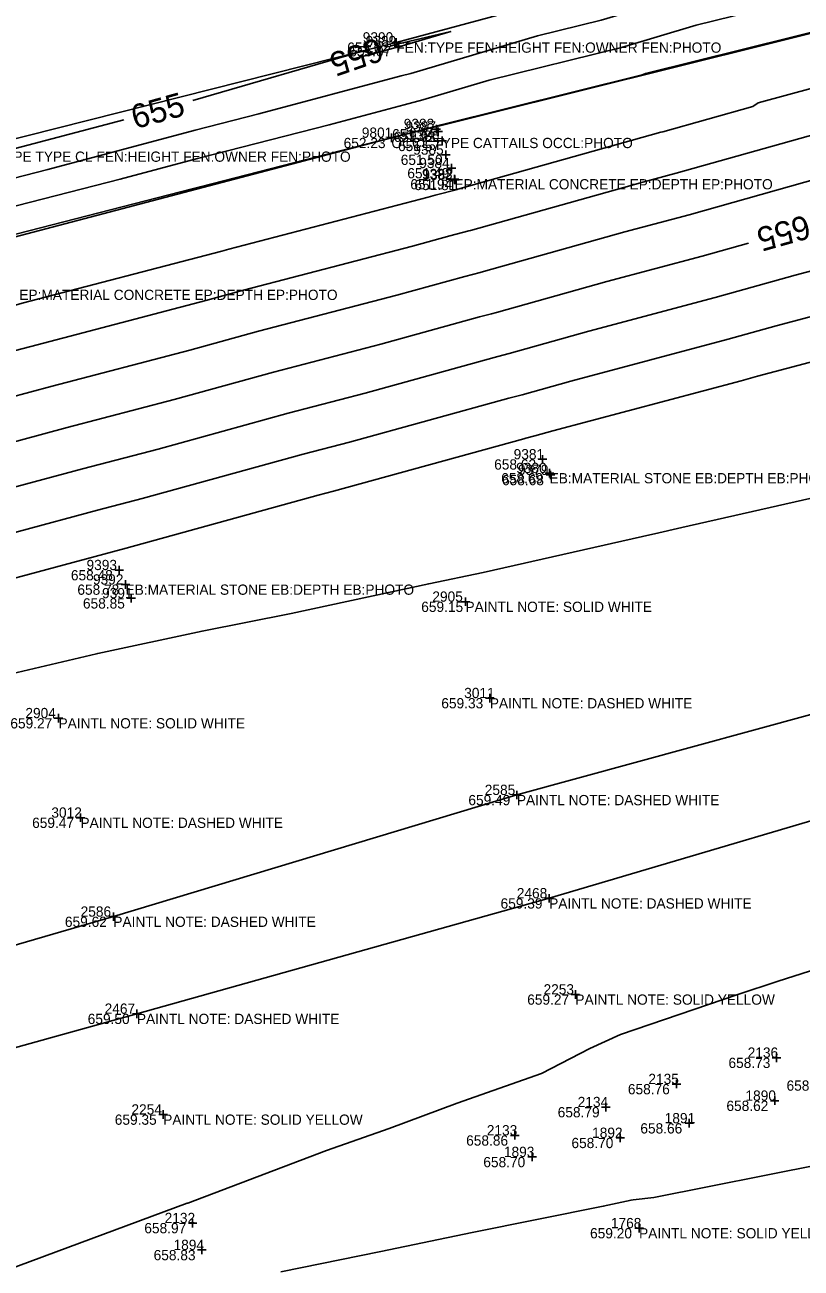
# Model space of a CAD drawing. Extents: x 2129350 to 2137777, y 657588 to 659885.
# Drawn here: x 2134795.8 to 2134886.7, y 659166.7 to 659312.2 of the extents above; entities that cross this region are included whole.
import ezdxf

# ---------------------------------------------------------------- set-up
doc = ezdxf.new("R2010")
doc.units = 0
for name, color, linetype in [('DT_X_Contour_Major', 7, 'Continuous'), ('DT_X_Contour_Minor', 7, 'Continuous'), ('DT_X_TIN_Hull', 7, 'Continuous'), ('PV_X_COP', 7, 'Continuous'), ('SV_X_Occupation_Line', 7, 'Continuous'), ('SV_X_Shot_Marker', 7, 'Continuous'), ('SV_X_Text_Comment', 7, 'Continuous'), ('SV_X_Text_Elevation', 7, 'Continuous'), ('SV_X_Text_Name', 7, 'Continuous')]:
    doc.layers.add(name, color=color, linetype=linetype)

msp = doc.modelspace()

# ---------------------------------------------------------------- linework, layer by layer
at = {"layer": 'DT_X_Contour_Major'}
for points in [[(2134839.53, 659309.65), (2134839.56, 659309.66), (2134845.65, 659311.45), (2134839.38, 659309.98), (2134838.56, 659309.72)], [(2134815.45, 659303.39), (2134835.85, 659309.3)], [(2134834.42, 659308.29), (2134839.53, 659309.65)], [(2134710.82, 659275.11), (2134722.14, 659278.72), (2134730.19, 659280.83), (2134741.44, 659283.77), (2134755.5, 659287.45), (2134775.47, 659292.74), (2134788.82, 659296.22), (2134790.45, 659296.66), (2134807.36, 659301.13)], [(2134784.02, 659260.55), (2134789.32, 659262.01), (2134800.75, 659265.09), (2134813.25, 659268.35), (2134824.88, 659271.56), (2134837.48, 659274.85), (2134849.02, 659278.03), (2134850.43, 659278.4), (2134851, 659278.55), (2134863.93, 659282.18), (2134875.1, 659285.15), (2134880.54, 659286.68)]]:
    msp.add_lwpolyline(points, dxfattribs=at)
at = {"layer": 'DT_X_Contour_Minor'}
for points in [[(2134699.42, 659268.63), (2134712.76, 659272.09), (2134713.84, 659272.45), (2134717.95, 659274.17), (2134736.51, 659279.04), (2134742.02, 659280.41), (2134759.71, 659285.04), (2134766.23, 659286.82), (2134783.58, 659291.38), (2134789.78, 659293.07), (2134791.58, 659293.55), (2134798.46, 659295.31), (2134815.72, 659299.91), (2134823.16, 659301.82), (2134839.85, 659306.26), (2134840.98, 659306.55), (2134855.81, 659310.93), (2134863.28, 659312.79), (2134880.29, 659317.84), (2134887.25, 659319.57)], [(2134889.82, 659316.01), (2134874.38, 659312.18), (2134865.67, 659309.6), (2134850.17, 659305.74), (2134842.4, 659303.44), (2134840.18, 659302.87), (2134831.43, 659300.54), (2134816.01, 659296.59), (2134806.93, 659294.17), (2134791.84, 659290.31), (2134790.89, 659290.05), (2134777.18, 659286.32), (2134768.19, 659283.96), (2134753, 659279.82), (2134744.06, 659277.47), (2134730.43, 659274.1), (2134720.3, 659271.44), (2134709.4, 659266.88)], [(2134891.42, 659312.22), (2134868.47, 659306.52), (2134868.06, 659306.4), (2134844.53, 659300.54), (2134843.83, 659300.34), (2134840.5, 659299.49), (2134839.71, 659299.27), (2134816.3, 659293.28), (2134815.39, 659293.03), (2134792.09, 659287.06), (2134791.99, 659287.04), (2134770.78, 659281.26), (2134770.15, 659281.1), (2134746.3, 659274.59), (2134746.09, 659274.54), (2134724.35, 659269.15), (2134722.66, 659268.7), (2134720.39, 659267.75), (2134709.21, 659264.82)], [(2134702.5, 659254.36), (2134725.66, 659260.59), (2134726.7, 659260.87), (2134748.27, 659266.68), (2134748.42, 659266.72), (2134771.59, 659273.08), (2134772.52, 659273.33), (2134794.7, 659279.43), (2134795.46, 659279.63), (2134818.85, 659285.74), (2134819.65, 659285.96), (2134843.02, 659292.06), (2134843.84, 659292.29), (2134846.43, 659292.97), (2134846.48, 659292.98), (2134870.25, 659299.65), (2134870.51, 659299.72), (2134881.04, 659302.68), (2134881.64, 659303.12), (2134895.16, 659306.79)], [(2134706.8, 659250.25), (2134726.55, 659255.56), (2134731.06, 659256.76), (2134749.39, 659261.7), (2134750.02, 659261.86), (2134769.68, 659267.27), (2134774.12, 659268.46), (2134792.9, 659273.62), (2134797.22, 659274.78), (2134816.98, 659279.94), (2134821.39, 659281.16), (2134841.17, 659286.32), (2134845.56, 659287.53), (2134847.77, 659288.11), (2134847.98, 659288.17), (2134868.14, 659293.83), (2134872.04, 659294.86), (2134892.65, 659300.66)], [(2134703.32, 659244.07), (2134711.11, 659246.14), (2134727.44, 659250.53), (2134735.43, 659252.66), (2134750.5, 659256.72), (2134751.61, 659257.01), (2134767.78, 659261.45), (2134775.72, 659263.59), (2134791.11, 659267.82), (2134798.99, 659269.93), (2134815.11, 659274.15), (2134823.14, 659276.36), (2134839.33, 659280.58), (2134847.29, 659282.78), (2134849.1, 659283.25), (2134849.49, 659283.36), (2134866.04, 659288.01), (2134873.57, 659290), (2134890.43, 659294.75)], [(2134705.11, 659234.04), (2134719.72, 659237.92), (2134729.22, 659240.48), (2134744.15, 659244.44), (2134752.73, 659246.75), (2134754.79, 659247.3), (2134763.96, 659249.82), (2134778.93, 659253.84), (2134787.52, 659256.21), (2134802.51, 659260.24), (2134811.38, 659262.55), (2134826.63, 659266.76), (2134835.64, 659269.11), (2134850.75, 659273.27), (2134851.76, 659273.54), (2134852.51, 659273.74), (2134861.82, 659276.36), (2134876.63, 659280.29), (2134886, 659282.92), (2134900.74, 659286.83)], [(2134706.01, 659229.02), (2134724.03, 659233.81), (2134730.11, 659235.45), (2134748.51, 659240.34), (2134753.84, 659241.77), (2134756.38, 659242.44), (2134762.06, 659244), (2134780.53, 659248.97), (2134785.73, 659250.4), (2134804.28, 659255.39), (2134809.52, 659256.76), (2134828.38, 659261.96), (2134833.79, 659263.37), (2134852.47, 659268.52), (2134853.1, 659268.68), (2134854.01, 659268.93), (2134859.71, 659270.53), (2134878.15, 659275.43), (2134883.78, 659277.01), (2134902.3, 659281.92)], [(2134706.91, 659224.01), (2134728.34, 659229.7), (2134731.01, 659230.42), (2134752.87, 659236.23), (2134754.96, 659236.79), (2134757.97, 659237.59), (2134760.15, 659238.19), (2134782.13, 659244.1), (2134783.94, 659244.6), (2134806.04, 659250.54), (2134807.65, 659250.96), (2134830.12, 659257.16), (2134831.94, 659257.63), (2134854.2, 659263.77), (2134854.43, 659263.83), (2134855.52, 659264.13), (2134857.6, 659264.71), (2134879.68, 659270.57), (2134881.56, 659271.1), (2134903.85, 659277.01)], [(2134708.88, 659216.82), (2134732.14, 659222.06), (2134735.18, 659222.69), (2134755.58, 659227.24), (2134755.62, 659227.25), (2134758.2, 659227.83), (2134764.28, 659229.25), (2134781.18, 659233.22), (2134790.18, 659235.32), (2134804.17, 659238.6), (2134804.31, 659238.64), (2134816.54, 659241.25), (2134826.95, 659243.32), (2134843.07, 659246.8), (2134849.45, 659248.09), (2134869.33, 659252.61), (2134869.5, 659252.64), (2134872.7, 659253.37), (2134895.12, 659258.47)], [(2134892.21, 659202.86), (2134883.98, 659200.25), (2134879.28, 659198.68), (2134865.55, 659194.01), (2134861.95, 659192.38), (2134856.28, 659189.44), (2134846.42, 659185.99), (2134838.43, 659183), (2134831.09, 659180.42), (2134814.85, 659174.27), (2134814.8, 659174.25), (2134792.28, 659165.92)], [(2134825.75, 659166.23), (2134837.46, 659168.59), (2134848.17, 659170.83), (2134863.52, 659173.91), (2134866.78, 659174.62), (2134867.02, 659174.67), (2134869.43, 659174.92), (2134889.08, 659178.81)]]:
    msp.add_lwpolyline(points, dxfattribs=at)
at = {"layer": 'DT_X_TIN_Hull'}
msp.add_lwpolyline([(2135530.59, 659503.78), (2135475.39, 659489.05), (2135416.67, 659473.77), (2135375.74, 659461.35), (2135332.28, 659448.99), (2135282.8, 659433.85), (2135234.45, 659419.66), (2135187.99, 659405.62), (2135140.1, 659391.95), (2135093.39, 659377.69), (2135039.16, 659363.4), (2134946.54, 659338.8), (2134928.12, 659333.86), (2134885.43, 659322.6), (2134839.28, 659310.17), (2134788.72, 659297.4), (2134742.32, 659285.27), (2134695.66, 659270.22), (2134671.45, 659264.13), (2134637.39, 659257.64), (2134592.77, 659246.33), (2134552.01, 659235.92), (2134498.13, 659222.44), (2134448.36, 659209.51)], dxfattribs=at)
at = {"layer": 'PV_X_COP'}
for points in [[(2134520.09, 659114.68), (2134568.13, 659128.65), (2134617.04, 659142.36), (2134664.66, 659155.43), (2134712.28, 659169.02), (2134760.57, 659182.99), (2134808.9, 659196.44), (2134857.18, 659209.96), (2134905, 659224.09), (2134953.16, 659237.82), (2135001.3, 659251.25), (2135048.97, 659264.98), (2135097.44, 659279.39), (2135145, 659292.73), (2135193.91, 659307.04), (2135241.76, 659320.98), (2135289.6, 659334.84), (2135337.5, 659347.93), (2135385.12, 659361.55), (2135434.03, 659374.73), (2135482.21, 659388.12), (2135530.34, 659401.09)], [(2135046.23, 659276.72), (2134998.09, 659262.4), (2134950.01, 659248.29), (2134901.68, 659235.27), (2134853.4, 659222.06), (2134806.14, 659207.81), (2134757.33, 659193.63), (2134709.1, 659180.43), (2134661.25, 659167.25), (2134613.17, 659153.43), (2134564.8, 659140.1), (2134516.96, 659126.54), (2134468.46, 659112.97), (2134420.69, 659099.3), (2134372.8, 659086.61), (2134323.79, 659072.7)]]:
    msp.add_lwpolyline(points, dxfattribs=at)
at = {"layer": 'SV_X_Occupation_Line'}
msp.add_lwpolyline([(2134406.75, 659176.4), (2134469.4, 659192.65), (2134470.91, 659203.28), (2134565.45, 659226.72), (2134662.6, 659252.21), (2134757.72, 659277.68), (2134838.71, 659299.01), (2134949.99, 659326.74)], dxfattribs=at)
at = {"layer": 'SV_X_Shot_Marker'}
for p, q in [((2134838.78, 659310.17), (2134839.78, 659310.17)), ((2134839.02, 659309.74), (2134840.02, 659309.74)), ((2134839.28, 659310.67), (2134839.28, 659309.67)), ((2134839.28, 659310.17), (2134839.28, 659310.17)), ((2134839.52, 659310.24), (2134839.52, 659309.24)), ((2134839.52, 659309.74), (2134839.52, 659309.74)), ((2134843.97, 659300.53), (2134843.97, 659299.53)), ((2134838.71, 659299.51), (2134838.71, 659298.51)), ((2134843.47, 659300.03), (2134844.47, 659300.03)), ((2134843.67, 659299.73), (2134844.67, 659299.73)), ((2134843.97, 659300.03), (2134843.97, 659300.03)), ((2134844.17, 659300.23), (2134844.17, 659299.23)), ((2134844.17, 659299.73), (2134844.17, 659299.73)), ((2134844.65, 659299.15), (2134844.65, 659298.15)), ((2134838.21, 659299.01), (2134839.21, 659299.01)), ((2134838.71, 659299.01), (2134838.71, 659299.01)), ((2134844.15, 659298.65), (2134845.15, 659298.65)), ((2134844.65, 659298.65), (2134844.65, 659298.65)), ((2134844.57, 659297.03), (2134845.57, 659297.03)), ((2134845.07, 659297.53), (2134845.07, 659296.53)), ((2134845.07, 659297.03), (2134845.07, 659297.03)), ((2134845.26, 659295.46), (2134846.26, 659295.46)), ((2134845.76, 659295.96), (2134845.76, 659294.96)), ((2134845.76, 659295.46), (2134845.76, 659295.46)), ((2134845.59, 659294.17), (2134846.59, 659294.17)), ((2134845.63, 659294.08), (2134846.63, 659294.08)), ((2134846.09, 659294.67), (2134846.09, 659293.67)), ((2134846.09, 659294.17), (2134846.09, 659294.17)), ((2134846.13, 659294.58), (2134846.13, 659293.58)), ((2134846.13, 659294.08), (2134846.13, 659294.08)), ((2134855.89, 659261.36), (2134856.89, 659261.36)), ((2134856.39, 659261.86), (2134856.39, 659260.86)), ((2134856.39, 659261.36), (2134856.39, 659261.36)), ((2134857.23, 659260.25), (2134857.23, 659259.25)), ((2134857.33, 659260.03), (2134857.33, 659259.03)), ((2134856.73, 659259.75), (2134857.73, 659259.75)), ((2134856.83, 659259.53), (2134857.83, 659259.53)), ((2134857.23, 659259.75), (2134857.23, 659259.75)), ((2134857.33, 659259.53), (2134857.33, 659259.53)), ((2134806.32, 659248.39), (2134807.32, 659248.39)), ((2134806.82, 659248.89), (2134806.82, 659247.89)), ((2134806.82, 659248.39), (2134806.82, 659248.39)), ((2134807.07, 659246.7), (2134808.07, 659246.7)), ((2134807.57, 659247.2), (2134807.57, 659246.2)), ((2134807.57, 659246.7), (2134807.57, 659246.7)), ((2134808.22, 659245.59), (2134808.22, 659244.59)), ((2134807.72, 659245.09), (2134808.72, 659245.09)), ((2134808.22, 659245.09), (2134808.22, 659245.09)), ((2134846.88, 659244.69), (2134847.88, 659244.69)), ((2134847.38, 659245.19), (2134847.38, 659244.19)), ((2134847.38, 659244.69), (2134847.38, 659244.69)), ((2134850.23, 659233.9), (2134850.23, 659232.9)), ((2134849.73, 659233.4), (2134850.73, 659233.4)), ((2134850.23, 659233.4), (2134850.23, 659233.4)), ((2134799.22, 659231.05), (2134800.22, 659231.05)), ((2134799.72, 659231.55), (2134799.72, 659230.55)), ((2134799.72, 659231.05), (2134799.72, 659231.05)), ((2134852.9, 659222.06), (2134853.9, 659222.06)), ((2134853.4, 659222.56), (2134853.4, 659221.56)), ((2134853.4, 659222.06), (2134853.4, 659222.06)), ((2134801.79, 659219.4), (2134802.79, 659219.4)), ((2134802.29, 659219.9), (2134802.29, 659218.9)), ((2134802.29, 659219.4), (2134802.29, 659219.4)), ((2134857.18, 659210.46), (2134857.18, 659209.46)), ((2134856.68, 659209.96), (2134857.68, 659209.96)), ((2134857.18, 659209.96), (2134857.18, 659209.96)), ((2134805.64, 659207.81), (2134806.64, 659207.81)), ((2134806.14, 659208.31), (2134806.14, 659207.31)), ((2134806.14, 659207.81), (2134806.14, 659207.81)), ((2134859.75, 659198.7), (2134860.75, 659198.7)), ((2134860.25, 659199.2), (2134860.25, 659198.2)), ((2134860.25, 659198.7), (2134860.25, 659198.7)), ((2134808.4, 659196.44), (2134809.4, 659196.44)), ((2134808.9, 659196.94), (2134808.9, 659195.94)), ((2134808.9, 659196.44), (2134808.9, 659196.44)), ((2134883.8, 659191.79), (2134883.8, 659190.79)), ((2134883.3, 659191.29), (2134884.3, 659191.29)), ((2134883.8, 659191.29), (2134883.8, 659191.29)), ((2134872.09, 659188.71), (2134872.09, 659187.71)), ((2134871.59, 659188.21), (2134872.59, 659188.21)), ((2134872.09, 659188.21), (2134872.09, 659188.21)), ((2134863.81, 659186.01), (2134863.81, 659185.01)), ((2134883.09, 659186.26), (2134884.09, 659186.26)), ((2134883.59, 659186.76), (2134883.59, 659185.76)), ((2134883.59, 659186.26), (2134883.59, 659186.26)), ((2134811.48, 659184.64), (2134812.48, 659184.64)), ((2134811.98, 659185.14), (2134811.98, 659184.14)), ((2134811.98, 659184.64), (2134811.98, 659184.64)), ((2134863.31, 659185.51), (2134864.31, 659185.51)), ((2134863.81, 659185.51), (2134863.81, 659185.51)), ((2134873.59, 659184.12), (2134873.59, 659183.12)), ((2134853.17, 659182.7), (2134853.17, 659181.7)), ((2134873.09, 659183.62), (2134874.09, 659183.62)), ((2134873.59, 659183.62), (2134873.59, 659183.62)), ((2134852.67, 659182.2), (2134853.67, 659182.2)), ((2134853.17, 659182.2), (2134853.17, 659182.2)), ((2134865.01, 659181.91), (2134866.01, 659181.91)), ((2134865.51, 659182.41), (2134865.51, 659181.41)), ((2134865.51, 659181.91), (2134865.51, 659181.91)), ((2134855.19, 659180.17), (2134855.19, 659179.17)), ((2134854.69, 659179.67), (2134855.69, 659179.67)), ((2134855.19, 659179.67), (2134855.19, 659179.67)), ((2134815.43, 659172.43), (2134815.43, 659171.43)), ((2134814.93, 659171.93), (2134815.93, 659171.93)), ((2134815.43, 659171.93), (2134815.43, 659171.93)), ((2134867.21, 659171.33), (2134868.21, 659171.33)), ((2134867.71, 659171.83), (2134867.71, 659170.83)), ((2134867.71, 659171.33), (2134867.71, 659171.33)), ((2134816, 659168.78), (2134817, 659168.78)), ((2134816.5, 659169.28), (2134816.5, 659168.28)), ((2134816.5, 659168.78), (2134816.5, 659168.78))]:
    msp.add_line(p, q, dxfattribs=at)

# ---------------------------------------------------------------- texts
at = {"layer": 'DT_X_Contour_Major'}
for rotation, p in [(199.0539, (2134837.13, 659310.81)), (15.6264, (2134808.7, 659300.01)), (195.6622, (2134887.29, 659290.03))]:
    msp.add_text('655', height=2.8, rotation=rotation, dxfattribs=at).set_placement(p)
at = {"layer": 'SV_X_Text_Comment'}
for s, p in [('FEN:TYPE FEN:HEIGHT FEN:OWNER FEN:PHOTO', (2134839.28, 659308.97)), ('OCCL:TYPE CATTAILS OCCL:PHOTO', (2134838.71, 659297.8)), ('FEN:TYPE TYPE CL FEN:HEIGHT FEN:OWNER FEN:PHOTO', (2134788.73, 659296.2)), ('EP:MATERIAL CONCRETE EP:DEPTH EP:PHOTO', (2134846.09, 659292.97)), ('EP:MATERIAL CONCRETE EP:DEPTH EP:PHOTO', (2134795.13, 659280.02)), ('EB:MATERIAL STONE EB:DEPTH EB:PHOTO', (2134857.23, 659258.55)), ('EB:MATERIAL STONE EB:DEPTH EB:PHOTO', (2134807.57, 659245.5)), ('PAINTL NOTE: SOLID WHITE', (2134847.38, 659243.49)), ('PAINTL NOTE: DASHED WHITE', (2134850.23, 659232.2)), ('PAINTL NOTE: SOLID WHITE', (2134799.72, 659229.85)), ('PAINTL NOTE: DASHED WHITE', (2134853.4, 659220.86)), ('PAINTL NOTE: DASHED WHITE', (2134802.29, 659218.2)), ('PAINTL NOTE: DASHED WHITE', (2134857.18, 659208.76)), ('PAINTL NOTE: DASHED WHITE', (2134806.14, 659206.61)), ('PAINTL NOTE: SOLID YELLOW', (2134860.25, 659197.5)), ('PAINTL NOTE: DASHED WHITE', (2134808.9, 659195.24)), ('PAINTL NOTE: SOLID YELLOW', (2134811.98, 659183.44)), ('PAINTL NOTE: SOLID YELLOW', (2134867.71, 659170.14))]:
    msp.add_text(s, height=1.2, dxfattribs=at).set_placement(p)
at = {"layer": 'SV_X_Text_Elevation'}
for s, p in [('655.02', (2134833.53, 659308.97)), ('655.07', (2134833.77, 659308.54)), ('651.94', (2134838.79, 659298.83)), ('651.93', (2134838.98, 659298.53)), ('652.23', (2134833.11, 659297.8)), ('651.57', (2134839.48, 659297.45)), ('651.50', (2134839.8, 659295.83)), ('651.49', (2134840.57, 659294.26)), ('651.94', (2134840.92, 659292.97)), ('651.81', (2134841.4, 659292.88)), ('658.62', (2134850.74, 659260.16)), ('658.69', (2134851.56, 659258.55)), ('658.68', (2134851.66, 659258.33)), ('658.48', (2134801.17, 659247.19)), ('658.78', (2134801.93, 659245.5)), ('658.85', (2134802.58, 659243.89)), ('659.15', (2134842.2, 659243.49)), ('659.33', (2134844.55, 659232.2)), ('659.27', (2134794.08, 659229.85)), ('659.49', (2134847.72, 659220.86)), ('659.47', (2134796.63, 659218.2)), ('659.39', (2134851.49, 659208.76)), ('659.62', (2134800.47, 659206.61)), ('659.27', (2134854.61, 659197.5)), ('659.50', (2134803.14, 659195.24)), ('658.73', (2134878.18, 659190.09)), ('658.58', (2134884.98, 659187.43)), ('658.76', (2134866.4, 659187.01)), ('658.79', (2134858.18, 659184.31)), ('658.62', (2134877.94, 659185.06)), ('659.35', (2134806.31, 659183.44)), ('658.66', (2134867.86, 659182.42)), ('658.86', (2134847.46, 659181)), ('658.70', (2134859.79, 659180.71)), ('658.70', (2134849.47, 659178.47)), ('658.97', (2134809.77, 659170.74)), ('659.20', (2134861.97, 659170.14)), ('658.83', (2134810.86, 659167.58))]:
    msp.add_text(s, height=1.2, dxfattribs=at).set_placement(p)
at = {"layer": 'SV_X_Text_Name'}
for s, p in [('9390', (2134835.35, 659310.17)), ('9389', (2134835.7, 659309.74)), ('9388', (2134840.15, 659300.03)), ('9387', (2134840.36, 659299.73)), ('9801', (2134835.24, 659299.01)), ('9386', (2134840.76, 659298.65)), ('9385', (2134841.26, 659297.03)), ('9384', (2134841.96, 659295.46)), ('9383', (2134842.29, 659294.17)), ('9382', (2134842.33, 659294.08)), ('9381', (2134853.02, 659261.36)), ('9380', (2134853.32, 659259.75)), ('9379', (2134853.53, 659259.53)), ('9393', (2134803, 659248.39)), ('9392', (2134803.75, 659246.7)), ('9391', (2134804.82, 659245.09)), ('2905', (2134843.5, 659244.69)), ('3011', (2134847.23, 659233.4)), ('2904', (2134795.84, 659231.05)), ('2585', (2134849.64, 659222.06)), ('3012', (2134798.88, 659219.4)), ('2468', (2134853.39, 659209.96)), ('2586', (2134802.31, 659207.81)), ('2253', (2134856.52, 659198.7)), ('2467', (2134805.12, 659196.44)), ('2136', (2134880.43, 659191.29)), ('2135', (2134868.8, 659188.21)), ('1890', (2134880.17, 659186.26)), ('2254', (2134808.26, 659184.64)), ('2134', (2134860.52, 659185.51)), ('1891', (2134870.71, 659183.62)), ('2133', (2134849.88, 659182.2)), ('1892', (2134862.21, 659181.91)), ('1893', (2134851.88, 659179.67)), ('2132', (2134812.15, 659171.93)), ('1768', (2134864.41, 659171.33)), ('1894', (2134813.19, 659168.78))]:
    msp.add_text(s, height=1.2, dxfattribs=at).set_placement(p)

doc.saveas('drawing.dxf')
